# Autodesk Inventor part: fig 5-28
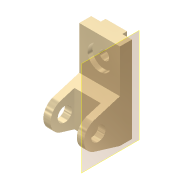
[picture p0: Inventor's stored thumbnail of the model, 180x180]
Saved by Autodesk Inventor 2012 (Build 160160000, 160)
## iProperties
Shininess: 65.0
Angle Display Precision: 2
Document Length Units: 11269
Document Angle Units: 11279
Document Time Units: 11290
Document Mass Units: 11283
Document Length Units Precision: 3
Document Angle Units Precision: 2
Created: 2001-11
Part Number: fig 5-28
Document SubType Name: Modeling
Designer: Renu Muthoo
Density: 1 g/cm^3
Material: Default
Density: 0.0
Volumn: 0.0
Area: 0.0
PropertySet Name: Model Information
Control State: 0
Master: False
Checked Out: False
Author: Renu Muthoo
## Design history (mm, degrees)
node "Sketch1"
sketch "Sketch2"
  geometry: L1 (33.257, 104.664)-(33.257, -75.336); L2 (33.257, -75.336)-(8.257, -75.336); L3 (8.257, -75.336)-(-45.451, -59.045); L4 (-45.451, -1.628)-(8.257, 14.664); L5 (8.257, 14.664)-(8.257, 104.664); L6 (8.257, 104.664)-(33.257, 104.664); C1 r 15 at (-36.743, -30.336); A1 r 30 centre (-36.743, -30.336) between (-45.451, -1.628) and (-45.451, -59.045)
  constraints: 12 end point, 2 centre point, 2 equal length, 2 parallel, 2 point on circle, 2 tangent, 1 coincident, 1 perpendicular, 1 vertical
  dimensions: "d0" = 180 distance of L1.start L1.end; "d1" = 30 radius of A1; "d2" = 25 distance of L5.end L1.start; "d3" = 45 distance from line of L2 A1.centre; "d4" = 70 distance from line of L1 A1.centre; "d5" = 30 diameter of C1
extrude "Extrusion1" new body sketch "Sketch2" distance "d6" = 85; taper "d7" = 0 deg
workplane "Work Plane1"
sketch "Sketch3"
  geometry: L1 (15, 62.364)-(70, 62.364); L2 (70, 62.364)-(70, -52.386); L3 (70, -52.386)-(15, -52.386); L4 (15, -52.386)-(15, 62.364); L5 (0, -45)-(0, -28.708) reference
  constraints: 8 end point, 2 parallel, 1 horizontal, 1 perpendicular
  dimensions: "d8" = 55 distance of L1.start L1.end; "d9" = 15 distance between parallel lines of L5 L4
extrude "Extrusion2" cut sketch "Sketch3" distance "d10" = 50; taper "d11" = 0 deg
sketch "Sketch4"
  geometry: L1 (0, 25)-(85, 25) reference; L2 (0, 0)-(0, 25) reference; L3 (20, 25)-(65, 25); L4 (65, 25)-(65, 35); L5 (65, 35)-(20, 35); L6 (20, 35)-(20, 25)
  constraints: 8 end point, 2 parallel, 1 horizontal, 1 perpendicular, 1 point on line
  dimensions: "d12" = 45 distance of L4.end L5.end; "d13" = 10 distance of L3.end L4.end; "d14" = 20 distance between parallel lines of L2 L6
extrude "Extrusion3" join sketch "Sketch4" stored distance "d15" = 50; taper "d16" = 0 deg
sketch "Sketch5"
  geometry: L1 (85, 0)-(85, 90) reference; L2 (0, 90)-(85, 90) reference; 1 further point
  dimensions: "d17" = 42 distance from line of L2 point (42.5, 48); "d18" = 42.5 distance from line of L1 point (42.5, 48)
hole "Hole1" sketch "Sketch5" at (42.5, 48) diameter "d19" = 20; stored, may be unused: countersink angle "d23" = 82 deg, drill point angle "d25" = 118 deg; dims "d20" = 6, "d21" = 50, "d22" = 10, "d24" = 8
workplane "Work Plane4"
body "Solid1"
other parameters: "d26" = 0
